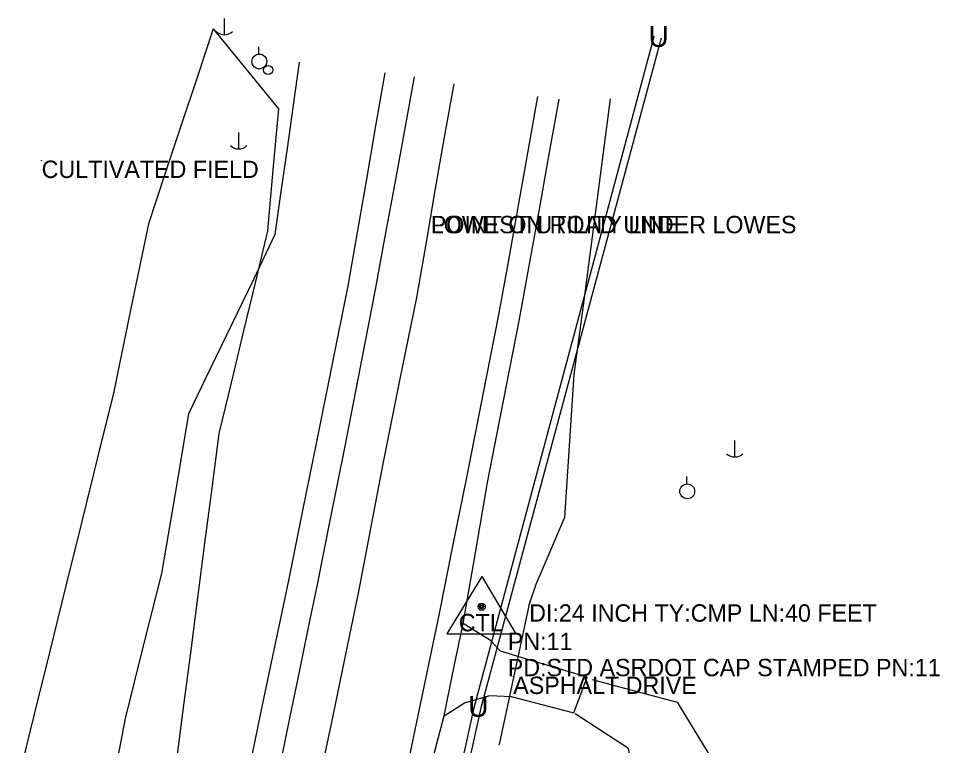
# Model space of a CAD drawing. Extents: x 1445297 to 1476720, y 2042269 to 2057889.
# Drawn here: x 1446242 to 1446506.8, y 2056413 to 2056622.2 of the extents above; entities that cross this region are included whole.
import ezdxf

# ---------------------------------------------------------------- set-up
doc = ezdxf.new("R2010")
doc.units = 0
for name, color, linetype in [('S_DITCHLINE', 7, 'Continuous'), ('S_DRG_PT_SYM', 7, 'Continuous'), ('S_DRIVEWAY', 7, 'Continuous'), ('S_EDGE_PAVEMENT', 7, 'Continuous'), ('S_ELECTRIC_UTILITIES_ANNOT', 7, 'Continuous'), ('S_FIBER_OPTIC_CABLE', 7, 'Continuous'), ('S_MSC_PT_SYM', 7, 'Continuous'), ('S_PAVEMENT_CROWN', 7, 'Continuous'), ('S_PRIMARY_CTL', 7, 'Continuous'), ('S_PRIMARY_CTL_ANNOT', 7, 'Continuous'), ('S_SHOULDER', 7, 'Continuous'), ('S_SIDE_DRAIN', 7, 'Continuous'), ('S_SIDE_DRAIN_ANNOT', 7, 'Continuous'), ('S_SURVEY_TEXT_ANNOT', 7, 'Continuous'), ('S_TREE', 7, 'Continuous'), ('S_UNDERGROUND_CABLE', 7, 'Continuous'), ('S_UTILITY_POLE', 7, 'Continuous'), ('S_UTL_PT_SYM', 7, 'Continuous')]:
    doc.layers.add(name, color=color, linetype=linetype)

msp = doc.modelspace()

# ---------------------------------------------------------------- linework, layer by layer
at = {"layer": 'S_DITCHLINE'}
for points in [[(1446322.7, 2056609.57), (1446320.96, 2056597.17), (1446319.22, 2056584.78), (1446317.48, 2056572.38), (1446315.74, 2056559.98), (1446309.54, 2056547.11), (1446303.34, 2056534.23), (1446297.14, 2056521.36), (1446290.94, 2056508.48), (1446287.04, 2056485.53), (1446283.14, 2056462.57), (1446277.91, 2056441.68), (1446272.69, 2056420.8), (1446268.75, 2056400.28)], [(1446412.15, 2056598.99), (1446409.54, 2056579.19), (1446406.94, 2056559.39), (1446404.33, 2056539.6), (1446401.72, 2056519.8), (1446400.34, 2056499.23), (1446398.96, 2056478.66), (1446390.73, 2056459.32), (1446388.83, 2056453.73)]]:
    msp.add_lwpolyline(points, dxfattribs=at)
at = {"layer": 'S_DRG_PT_SYM'}
for points in [[(1446388.83, 2056453.67), (1446388.83, 2056453.72), (1446388.83, 2056453.67), (1446388.78, 2056453.67), (1446388.83, 2056453.67), (1446388.83, 2056453.62), (1446388.83, 2056453.67), (1446388.88, 2056453.67)], [(1446380.19, 2056413.39), (1446380.19, 2056413.44), (1446380.19, 2056413.39), (1446380.14, 2056413.39), (1446380.19, 2056413.39), (1446380.19, 2056413.34), (1446380.19, 2056413.39), (1446380.24, 2056413.39)]]:
    msp.add_lwpolyline(points, dxfattribs=at)
at = {"layer": 'S_DRIVEWAY'}
for points in [[(1446364.36, 2056421.63), (1446370.25, 2056425.3), (1446377.49, 2056427.43), (1446383.67, 2056427.13), (1446401.68, 2056422.49), (1446405.49, 2056432.69), (1446387.77, 2056437.99), (1446380.62, 2056440.16), (1446377.74, 2056443.26), (1446369.91, 2056448.15)], [(1446406.93, 2056432.04), (1446419.15, 2056428.81), (1446431.37, 2056425.57), (1446440.18, 2056411.01), (1446439.11, 2056388.41), (1446438.04, 2056365.81), (1446426.08, 2056363.05), (1446423.06, 2056380.81), (1446420.03, 2056398.57), (1446417.39, 2056412.23), (1446402.02, 2056422.13)]]:
    msp.add_lwpolyline(points, dxfattribs=at)
at = {"layer": 'S_EDGE_PAVEMENT'}
for points in [[(1446317.51, 2056408.61), (1446320.15, 2056421.41), (1446322.78, 2056434.21), (1446325.42, 2056447.01), (1446328.05, 2056459.81), (1446331.94, 2056479.22), (1446335.83, 2056498.63), (1446340.24, 2056521.4), (1446344.65, 2056544.18), (1446347.47, 2056559.47), (1446350.28, 2056574.76), (1446353.09, 2056590.05), (1446355.9, 2056605.34)], [(1446352.78, 2056401.97), (1446357.85, 2056426.25), (1446362.92, 2056450.52), (1446366.94, 2056470.34), (1446370.96, 2056490.15), (1446375.56, 2056513.55), (1446380.16, 2056536.96), (1446382.96, 2056552.64), (1446385.76, 2056568.32), (1446388.56, 2056584), (1446391.35, 2056599.68)]]:
    msp.add_lwpolyline(points, dxfattribs=at)
at = {"layer": 'S_FIBER_OPTIC_CABLE'}
for p, q in [((1446424.63, 2056616.87), (1446372.97, 2056423.91)), ((1446372.97, 2056423.91), (1446319.44, 2056184.59))]:
    msp.add_line(p, q, dxfattribs=at)
at = {"layer": 'S_MSC_PT_SYM'}
for points in [[(1446248.68, 2056581.26), (1446248.68, 2056581.31), (1446248.68, 2056581.26), (1446248.62, 2056581.26), (1446248.68, 2056581.26), (1446248.68, 2056581.21), (1446248.68, 2056581.26), (1446248.73, 2056581.26)], [(1446360.55, 2056565.37), (1446360.55, 2056565.42), (1446360.55, 2056565.37), (1446360.5, 2056565.37), (1446360.55, 2056565.37), (1446360.55, 2056565.32), (1446360.55, 2056565.37), (1446360.6, 2056565.37)], [(1446384.26, 2056432.87), (1446384.26, 2056432.92), (1446384.26, 2056432.87), (1446384.21, 2056432.87), (1446384.26, 2056432.87), (1446384.26, 2056432.82), (1446384.26, 2056432.87), (1446384.31, 2056432.87)]]:
    msp.add_lwpolyline(points, dxfattribs=at)
at = {"layer": 'S_PAVEMENT_CROWN'}
msp.add_lwpolyline([(1446329.35, 2056406.76), (1446331.97, 2056419.3), (1446334.59, 2056431.83), (1446337.2, 2056444.37), (1446339.82, 2056456.9), (1446343.33, 2056475.49), (1446346.85, 2056494.07), (1446351.67, 2056518), (1446356.5, 2056541.93), (1446359.18, 2056557.28), (1446361.86, 2056572.63), (1446364.54, 2056587.98), (1446367.23, 2056603.33)], dxfattribs=at)
at = {"layer": 'S_PRIMARY_CTL'}
for p, q in [((1446375.19, 2056461.68), (1446365.16, 2056445.16)), ((1446375.19, 2056461.68), (1446385.01, 2056445.16)), ((1446365.16, 2056445.16), (1446385.01, 2056445.16))]:
    msp.add_line(p, q, dxfattribs=at)
for radius in [1.04, 0.609, 0.344]:
    msp.add_circle((1446375.19, 2056452.98), radius, dxfattribs=at)
at = {"layer": 'S_SHOULDER'}
for points in [[(1446309.16, 2056410.15), (1446311.82, 2056422.86), (1446314.49, 2056435.58), (1446317.16, 2056448.29), (1446319.82, 2056461), (1446323.8, 2056480.68), (1446327.77, 2056500.35), (1446332.28, 2056522.8), (1446336.8, 2056545.24), (1446339.47, 2056560.57), (1446342.13, 2056575.89), (1446344.79, 2056591.22), (1446347.46, 2056606.55)], [(1446358.7, 2056400.23), (1446364.36, 2056421.63), (1446367.13, 2056434.89), (1446369.91, 2056448.15), (1446373.38, 2056468.45), (1446376.84, 2056488.74), (1446381.46, 2056512.18), (1446386.07, 2056535.62), (1446388.92, 2056551.45), (1446391.76, 2056567.28), (1446394.61, 2056583.12), (1446397.45, 2056598.95)]]:
    msp.add_lwpolyline(points, dxfattribs=at)
at = {"layer": 'S_SIDE_DRAIN'}
msp.add_line((1446388.83, 2056453.67), (1446380.19, 2056413.39), dxfattribs=at)
at = {"layer": 'S_TREE'}
for points in [[(1446298.01, 2056619.18), (1446293.35, 2056605.16), (1446288.69, 2056591.14), (1446284.03, 2056577.12), (1446279.36, 2056563.1), (1446274.34, 2056538.74), (1446269.32, 2056514.38), (1446264.77, 2056495.92), (1446260.22, 2056477.47), (1446255.66, 2056459.01), (1446251.11, 2056440.55), (1446246.56, 2056422.09), (1446242.01, 2056403.64)], [(1446298.01, 2056619.18), (1446307.38, 2056607.66), (1446316.75, 2056596.14), (1446315.18, 2056578.6), (1446313.62, 2056561.06), (1446310.12, 2056546.5), (1446306.62, 2056531.93), (1446303.12, 2056517.37), (1446299.62, 2056502.8), (1446297.58, 2056487.04), (1446295.53, 2056471.27), (1446293.49, 2056455.51), (1446291.45, 2056439.75), (1446289.4, 2056423.98), (1446287.36, 2056408.22)]]:
    msp.add_lwpolyline(points, dxfattribs=at)
at = {"layer": 'S_UNDERGROUND_CABLE'}
for p, q in [((1446426.78, 2056616.51), (1446374.96, 2056423.86)), ((1446374.96, 2056423.86), (1446321.29, 2056184.23))]:
    msp.add_line(p, q, dxfattribs=at)
at = {"layer": 'S_UTILITY_POLE'}
for p, q in [((1446301.16, 2056622.15), (1446301.16, 2056617.43)), ((1446311.16, 2056611.91), (1446311.16, 2056614.01)), ((1446305.29, 2056589.34), (1446305.29, 2056584.62)), ((1446447.88, 2056500.76), (1446447.88, 2056496.03)), ((1446434.15, 2056488.28), (1446434.15, 2056490.39))]:
    msp.add_line(p, q, dxfattribs=at)
for centre, radius in [((1446311.28, 2056609.77), 2.13), ((1446313.81, 2056607.3), 1.31), ((1446434.27, 2056486.14), 2.13)]:
    msp.add_circle(centre, radius, dxfattribs=at)
for centre in [(1446301.22, 2056620.85), (1446305.35, 2056588.04), (1446447.95, 2056499.45)]:
    msp.add_arc(centre, 3.41, 226.3972, 313.6028, dxfattribs=at)
at = {"layer": 'S_UTL_PT_SYM'}
for points in [[(1446424.63, 2056616.87), (1446424.63, 2056616.92), (1446424.63, 2056616.87), (1446424.58, 2056616.87), (1446424.63, 2056616.87), (1446424.63, 2056616.82), (1446424.63, 2056616.87), (1446424.68, 2056616.87)], [(1446360.55, 2056565.37), (1446360.55, 2056565.42), (1446360.55, 2056565.37), (1446360.5, 2056565.37), (1446360.55, 2056565.37), (1446360.55, 2056565.32), (1446360.55, 2056565.37), (1446360.6, 2056565.37)], [(1446372.97, 2056423.91), (1446372.97, 2056423.96), (1446372.97, 2056423.91), (1446372.92, 2056423.91), (1446372.97, 2056423.91), (1446372.97, 2056423.86), (1446372.97, 2056423.91), (1446373.02, 2056423.91)]]:
    msp.add_lwpolyline(points, dxfattribs=at)

# ---------------------------------------------------------------- texts
at = {"layer": 'S_ELECTRIC_UTILITIES_ANNOT'}
msp.add_text('LOWEST UTILITY LINE', height=5, dxfattribs=at).set_placement((1446360.55, 2056560.37))
at = {"layer": 'S_PRIMARY_CTL'}
msp.add_text('CTL', height=5, dxfattribs=at).set_placement((1446368.6, 2056445.9))
at = {"layer": 'S_PRIMARY_CTL_ANNOT'}
for s, p in [('PN:11', (1446382.69, 2056440.48)), ('PD:STD ASRDOT CAP STAMPED PN:11', (1446382.69, 2056432.98))]:
    msp.add_text(s, height=5, dxfattribs=at).set_placement(p)
at = {"layer": 'S_SIDE_DRAIN_ANNOT'}
msp.add_text('DI:24 INCH TY:CMP LN:40 FEET', height=5, dxfattribs=at).set_placement((1446388.83, 2056448.67))
at = {"layer": 'S_SURVEY_TEXT_ANNOT'}
for s, p in [('CULTIVATED FIELD', (1446248.68, 2056576.26)), ('POINT ON ROAD UNDER LOWES', (1446360.55, 2056560.37)), ('ASPHALT DRIVE', (1446384.26, 2056427.87))]:
    msp.add_text(s, height=5, dxfattribs=at).set_placement(p)
at = {"layer": 'S_UTL_PT_SYM'}
for p in [(1446423.15, 2056613.96), (1446371.33, 2056421.31)]:
    msp.add_text('U', height=6, dxfattribs=at).set_placement(p)

doc.saveas('drawing.dxf')
